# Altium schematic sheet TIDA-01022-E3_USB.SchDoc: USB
size 431 x 279 mm; Date: Not shown in title block; ApprovedBy: Not shown in title block; CheckedBy: Not shown in title block; Author: Not shown in title block; CompanyName: Not shown in title block; DrawnBy: Avinash N; Engineer: Not shown in title block; Organization: Not shown in title block; Address1: Not shown in title block; Address2: Not shown in title block; Address3: Not shown in title block; Address4: Not shown in title block; DocumentNumber: 1; Revision: Use project parameter SCH_Rev; SheetNumber: 16; SheetTotal: 26; PageSetup: Record=PageOptions¦CenterHorizontal=True¦CenterVertical=True¦PrintScale=1.00¦XCorrection=1.00¦YCorrection=1.00¦PrintKind=0¦BorderSize=5000000¦LeftOffset=0¦BottomOffset=0¦Orientation=2¦PaperLength=1000¦PaperWidth=1000¦Scale=100¦PaperSource=15¦PrintQuality=600¦MediaType=1¦DitherType=10¦PaperKind=Letter¦PrintScaleMode=1
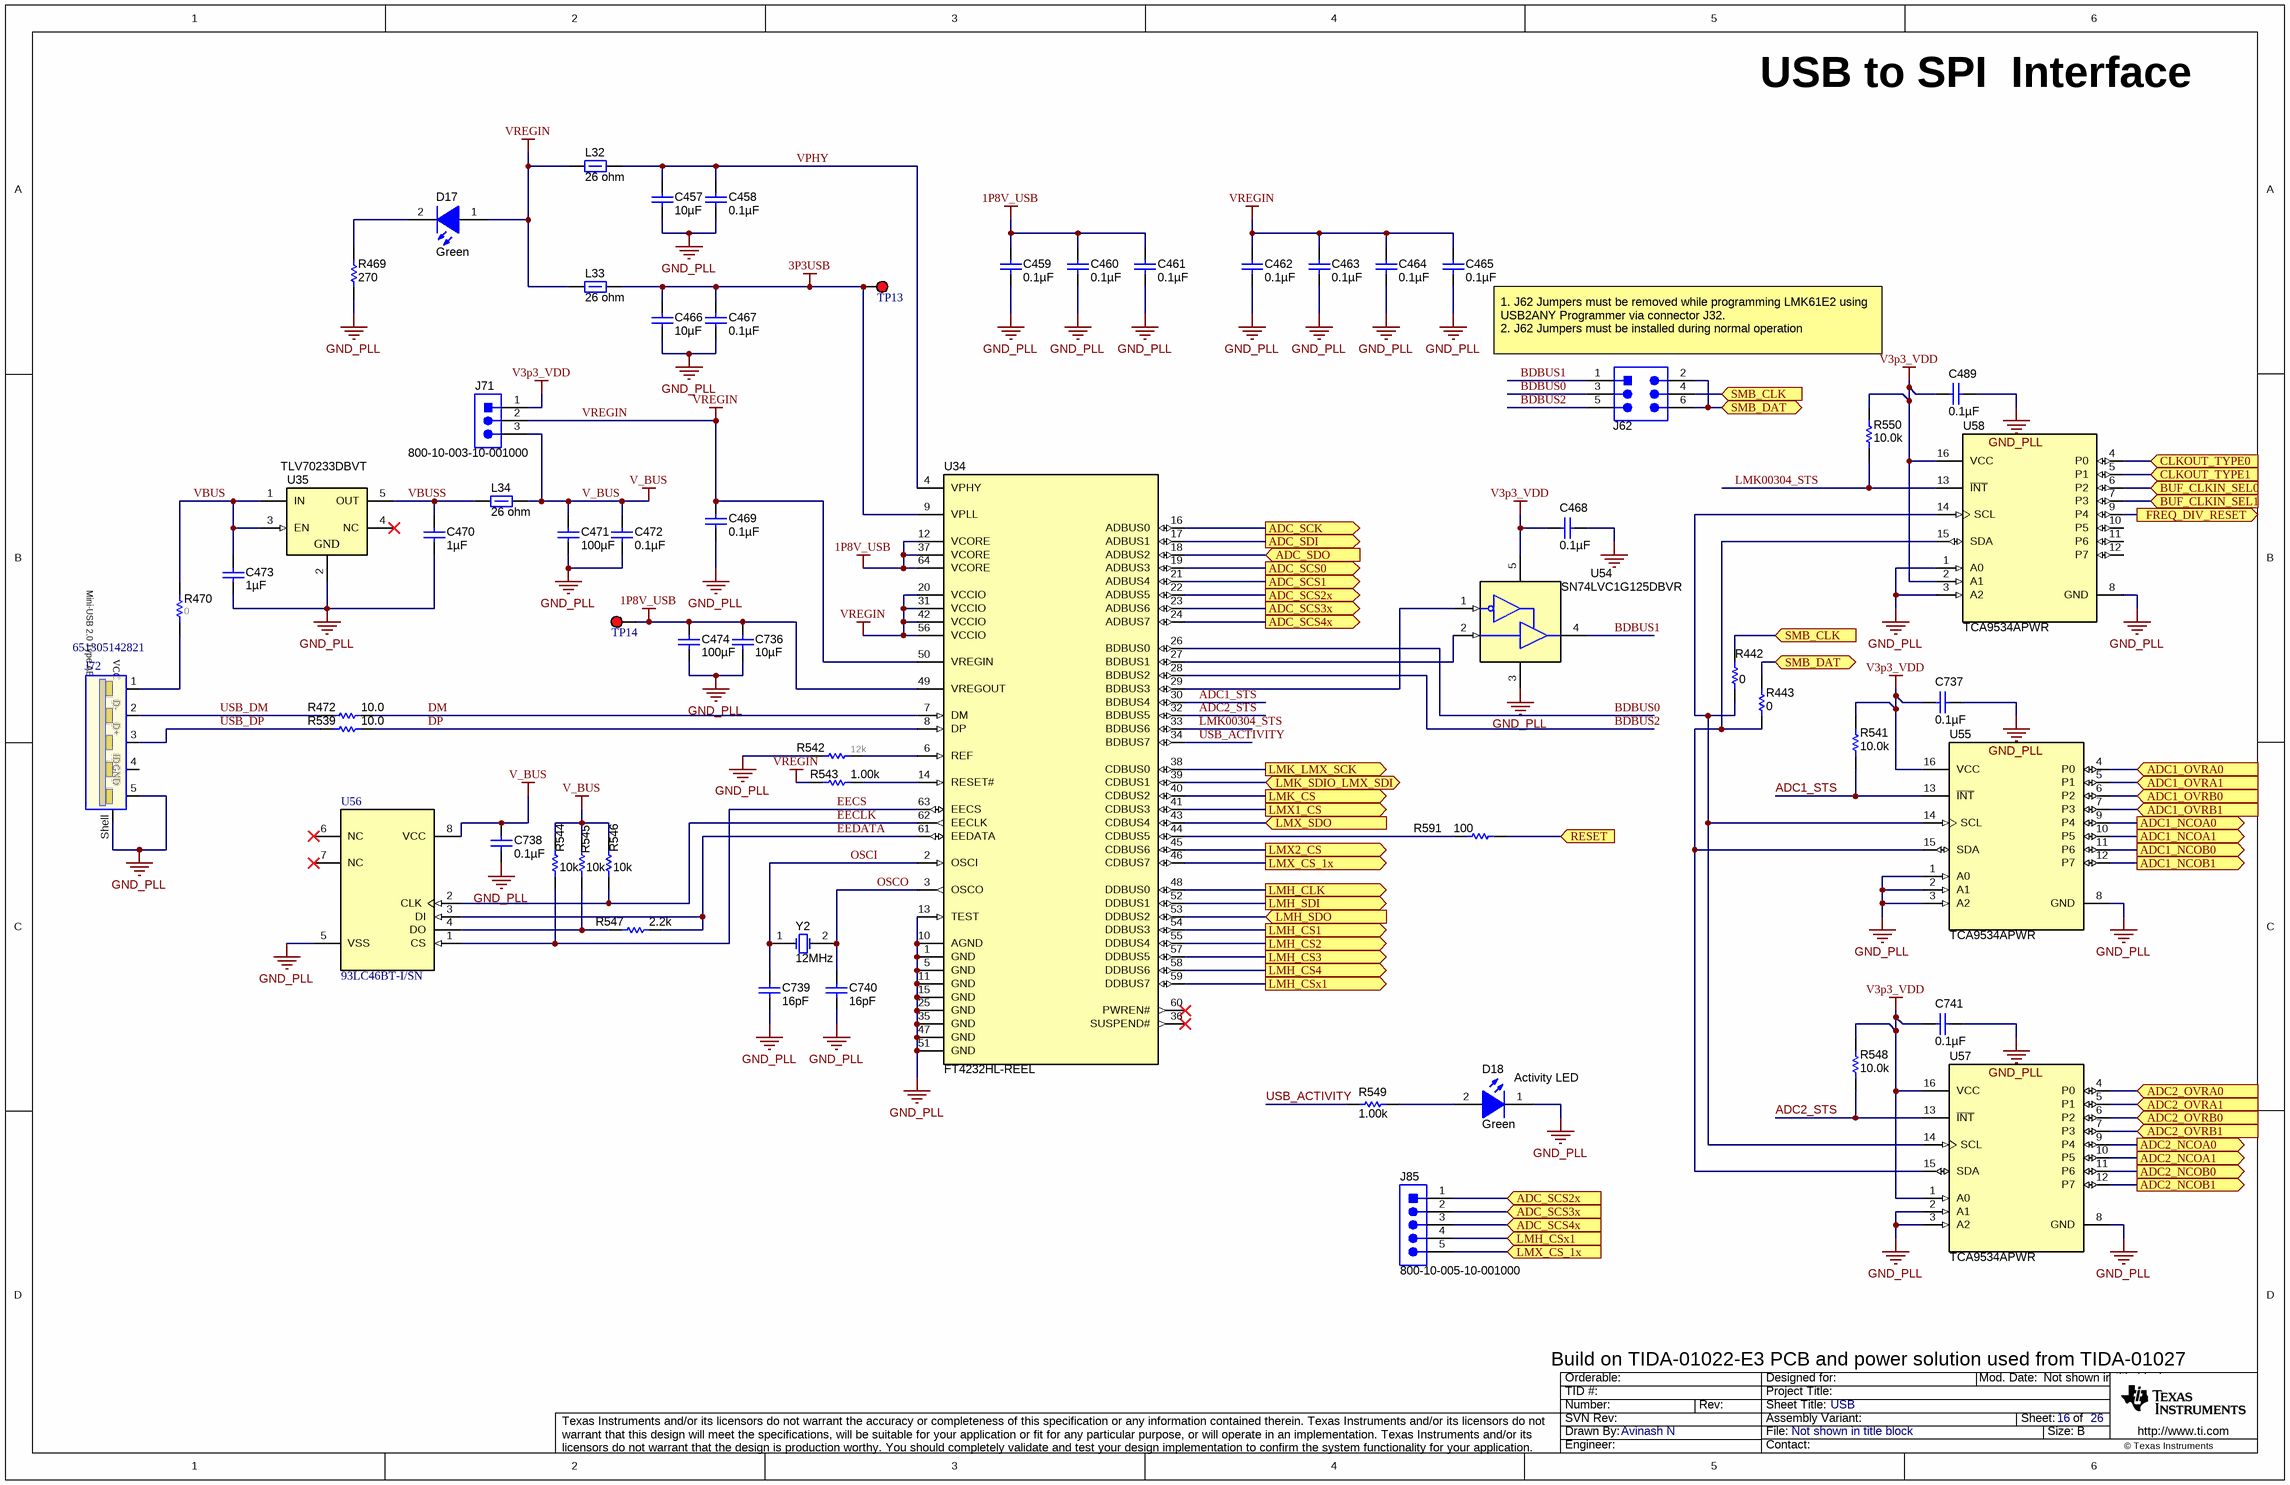
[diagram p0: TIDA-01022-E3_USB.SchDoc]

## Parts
C457  ValueDisplayed: 10µF  [0603]  (hidden comment: GRM188R61A106ME69D)
C458  ValueDisplayed: 0.1µF  [0603]  (hidden comment: C0603C104J3RACTU)
C459  ValueDisplayed: 0.1µF  [0603]  (hidden comment: C0603C104J3RACTU)
C460  ValueDisplayed: 0.1µF  [0603]  (hidden comment: C0603C104J3RACTU)
C461  ValueDisplayed: 0.1µF  [0603]  (hidden comment: C0603C104J3RACTU)
C462  ValueDisplayed: 0.1µF  [0603]  (hidden comment: C0603C104J3RACTU)
C463  ValueDisplayed: 0.1µF  [0603]  (hidden comment: C0603C104J3RACTU)
C464  ValueDisplayed: 0.1µF  [0603]  (hidden comment: C0603C104J3RACTU)
C465  ValueDisplayed: 0.1µF  [0603]  (hidden comment: C0603C104J3RACTU)
C466  ValueDisplayed: 10µF  [0603]  (hidden comment: GRM188R61A106ME69D)
C467  ValueDisplayed: 0.1µF  [0603]  (hidden comment: C0603C104J3RACTU)
C468  ValueDisplayed: 0.1µF  [0603]  (hidden comment: C0603C104J3RACTU)
C469  ValueDisplayed: 0.1µF  [0603]  (hidden comment: C0603C104J3RACTU)
C470  ValueDisplayed: 1µF  [0603]  (hidden comment: C1608X7R1C105K080AC)
C471  ValueDisplayed: 100µF  [1210_270]  (hidden comment: GRM32ER61A107ME20L)
C472  ValueDisplayed: 0.1µF  [0603]  (hidden comment: C0603C104J3RACTU)
C473  ValueDisplayed: 1µF  [0603]  (hidden comment: C1608X7R1C105K080AC)
C474  ValueDisplayed: 100µF  [1210_270]  (hidden comment: GRM32ER61A107ME20L)
C489  ValueDisplayed: 0.1µF  [0603]  (hidden comment: C0603C104J3RACTU)
C736  ValueDisplayed: 10µF  [0603]  (hidden comment: GRM188R61A106ME69D)
C737  ValueDisplayed: 0.1µF  [0603]  (hidden comment: C0603C104J3RACTU)
C738  ValueDisplayed: 0.1µF  [0603]  (hidden comment: C0603C104J3RACTU)
C739  ValueDisplayed: 16pF  [0603]  (hidden comment: GRM1885C2A160JA01D)
C740  ValueDisplayed: 16pF  [0603]  (hidden comment: GRM1885C2A160JA01D)
C741  ValueDisplayed: 0.1µF  [0603]  (hidden comment: C0603C104J3RACTU)
D17  value Green  [LTST-C191_Green]  (hidden comment: LTST-C191TGKT)
D18  value Green  [WL-SMCW_Green_0805]  (hidden comment: 150080GS75000)
J62  802-10-006-10-001000  [Mill-Max_802-10-006-10-001000]  (value not drawn)
J71  800-10-003-10-001000  [Mill-Max_800-10-003-10-001000]
J72  651305142821  [651305142821]
J85  800-10-005-10-001000  [Mill-Max_800-10-005-10-001000]
L32  ValueDisplayed: 26 ohm  [0603]  (hidden comment: BLM18SG260TN1D)
L33  ValueDisplayed: 26 ohm  [0603]  (hidden comment: BLM18SG260TN1D)
L34  ValueDisplayed: 26 ohm  [0603]  (hidden comment: BLM18SG260TN1D)
R442  ValueDisplayed: 0  [0603]  (hidden comment: CRCW06030000Z0EA)
R443  ValueDisplayed: 0  [0603]  (hidden comment: CRCW06030000Z0EA)
R469  ValueDisplayed: 270  [0603]  (hidden comment: CRCW0603270RJNEA)
R470  value 0  [0603]  (hidden comment: CRCW06030000Z0EA)
R472  ValueDisplayed: 10.0  [0603]  (hidden comment: CRCW060310R0FKEAHP)
R539  ValueDisplayed: 10.0  [0603]  (hidden comment: CRCW060310R0FKEAHP)
R541  ValueDisplayed: 10.0k  [1206]  (hidden comment: RC1206FR-0710KL)
R542  value 12k  [0603]  (hidden comment: CRCW060312K0JNEA)
R543  ValueDisplayed: 1.00k  [0603]  (hidden comment: CRCW06031K00FKEA)
R544  ValueDisplayed: 10k  [0603]  (hidden comment: CRCW060310K0JNEA)
R545  ValueDisplayed: 10k  [0603]  (hidden comment: CRCW060310K0JNEA)
R546  ValueDisplayed: 10k  [0603]  (hidden comment: CRCW060310K0JNEA)
R547  ValueDisplayed: 2.2k  [0603]  (hidden comment: CRCW06032K20JNEA)
R548  ValueDisplayed: 10.0k  [1206]  (hidden comment: RC1206FR-0710KL)
R549  ValueDisplayed: 1.00k  [0603]  (hidden comment: CRCW06031K00FKEA)
R550  ValueDisplayed: 10.0k  [1206]  (hidden comment: RC1206FR-0710KL)
R591  ValueDisplayed: 100  [0603]  (hidden comment: RC0603FR-07100RL)
TP13  5000  [Keystone5000]  (value not drawn)
TP14  5000  [Keystone5000]  (value not drawn)
U34  FT4232HL-REEL  [LQFP64_N]
U35  TLV70233DBVT  [DBV0005A_N]
U54  SN74LVC1G125DBVR  [DBV0005A_N]
U55  TCA9534APWR  [PW0016A_N]
U56  93LC46BT-I/SN  [SOIC-8]
U57  TCA9534APWR  [PW0016A_N]
U58  TCA9534APWR  [PW0016A_N]
Y2  Frequency: 12MHz  [XTAL_ABM3]  (hidden comment: ABM3-12.000MHZ-D2Y-T)

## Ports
ADC1_NCOA0 (out), ADC1_NCOA1 (out), ADC1_NCOB0 (out), ADC1_NCOB1 (out), ADC1_OVRA0 (in), ADC1_OVRA1 (in), ADC1_OVRB0 (in), ADC1_OVRB1 (in), ADC2_NCOA0 (out), ADC2_NCOA1 (out), ADC2_NCOB0 (out), ADC2_NCOB1 (out), ADC2_OVRA0 (in), ADC2_OVRA1 (in), ADC2_OVRB0 (in), ADC2_OVRB1 (in), ADC_SCK (out), ADC_SCS0 (out), ADC_SCS1 (out), ADC_SCS2x (in), ADC_SCS2x (out), ADC_SCS3x (in), ADC_SCS3x (out), ADC_SCS4x (in), ADC_SCS4x (out), ADC_SDI (out), ADC_SDO (in), BUF_CLKIN_SEL0 (in), BUF_CLKIN_SEL1 (in), CLKOUT_TYPE0 (in), CLKOUT_TYPE1 (in), FREQ_DIV_RESET (out), LMH_CLK (out), LMH_CS1 (out), LMH_CS2 (out), LMH_CS3 (out), LMH_CS4 (out), LMH_CSx1 (in), LMH_CSx1 (out), LMH_SDI (out), LMH_SDO (in), LMK_CS (out), LMK_LMX_SCK (out), LMK_SDIO_LMX_SDI (bidir), LMX1_CS (out), LMX2_CS (out), LMX_CS_1x (in), LMX_CS_1x (out), LMX_SDO (in), RESET (in), SMB_CLK (in), SMB_DAT (bidir)

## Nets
1P8V_USB: C459.2 C460.2 C461.2 C474.1 C736.1 TP14.1 U34.12(VCORE) U34.37(VCORE) U34.49(VREGOUT) U34.64(VCORE)
3P3USB: C466.1 C467.2 L33.2 TP13.1 U34.9(VPLL)
GND_PLL: C457.2 C458.1 C459.1 C460.1 C461.1 C462.1 C463.1 C464.1 C465.1 C466.2 C467.1 C468.1 C469.1 C470.2 C471.2 C472.1 C473.2 C474.2 C489.1 C736.2 C737.1 C738.1 C739.2 C740.2 C741.1 D18.1(K) J72.5(GND) J72.Shell R469.1 R542.2 U34.1(GND) U34.5(GND) U34.10(AGND) U34.11(GND) U34.13(TEST) U34.15(GND) U34.25(GND) U34.35(GND) U34.47(GND) U34.51(GND) U35.2(GND) U54.3(GND) U55.1(A0) U55.2(A1) U55.3(A2) U55.8(GND) U56.5(VSS) U57.2(A1) U57.3(A2) U57.8(GND) U58.1(A0) U58.3(A2) U58.8(GND)
V3p3_VDD: C468.2 C489.2 C737.2 C741.2 J71.1 R541.2 R548.2 R550.2 U54.5(VCC) U55.16(VCC) U57.1(A0) U57.16(VCC) U58.2(A1) U58.16(VCC)
V_BUS: C471.1 C472.2 C738.2 J71.3 L34.2 R544.2 R545.2 R546.2 U56.8(VCC)
VREGIN: C462.2 C463.2 C464.2 C465.2 C469.2 D17.1(A) J71.2 L32.1 L33.1 R543.1 U34.20(VCCIO) U34.31(VCCIO) U34.42(VCCIO) U34.50(VREGIN) U34.56(VCCIO)
ADC1_NCOA0: U55.9(P4) ; port ADC1_NCOA0
ADC1_NCOA1: U55.10(P5) ; port ADC1_NCOA1
ADC1_NCOB0: U55.11(P6) ; port ADC1_NCOB0
ADC1_NCOB1: U55.12(P7) ; port ADC1_NCOB1
ADC1_OVRA0: U55.4(P0) ; port ADC1_OVRA0
ADC1_OVRA1: U55.5(P1) ; port ADC1_OVRA1
ADC1_OVRB0: U55.6(P2) ; port ADC1_OVRB0
ADC1_OVRB1: U55.7(P3) ; port ADC1_OVRB1
ADC1_STS: R541.1 U34.30(BDBUS4) U55.13(~{INT})
ADC2_NCOA0: U57.9(P4) ; port ADC2_NCOA0
ADC2_NCOA1: U57.10(P5) ; port ADC2_NCOA1
ADC2_NCOB0: U57.11(P6) ; port ADC2_NCOB0
ADC2_NCOB1: U57.12(P7) ; port ADC2_NCOB1
ADC2_OVRA0: U57.4(P0) ; port ADC2_OVRA0
ADC2_OVRA1: U57.5(P1) ; port ADC2_OVRA1
ADC2_OVRB0: U57.6(P2) ; port ADC2_OVRB0
ADC2_OVRB1: U57.7(P3) ; port ADC2_OVRB1
ADC2_STS: R548.1 U34.32(BDBUS5) U57.13(~{INT})
ADC_SCK: U34.16(ADBUS0) ; port ADC_SCK
ADC_SCS0: U34.19(ADBUS3) ; port ADC_SCS0
ADC_SCS1: U34.21(ADBUS4) ; port ADC_SCS1
ADC_SCS2x: J85.1 U34.22(ADBUS5) ; port ADC_SCS2x
ADC_SCS3x: J85.2 U34.23(ADBUS6) ; port ADC_SCS3x
ADC_SCS4x: J85.3 U34.24(ADBUS7) ; port ADC_SCS4x
ADC_SDI: U34.17(ADBUS1) ; port ADC_SDI
ADC_SDO: U34.18(ADBUS2) ; port ADC_SDO
BDBUS0: J62.3 U34.26(BDBUS0)
BDBUS1: J62.1 U54.4(Y)
BDBUS2: J62.5 U34.28(BDBUS2)
BUF_CLKIN_SEL0: U58.6(P2) ; port BUF_CLKIN_SEL0
BUF_CLKIN_SEL1: U58.7(P3) ; port BUF_CLKIN_SEL1
CLKOUT_TYPE0: U58.4(P0) ; port CLKOUT_TYPE0
CLKOUT_TYPE1: U58.5(P1) ; port CLKOUT_TYPE1
DM: R472.2 U34.7(DM)
DP: R539.2 U34.8(DP)
EECLK: R546.1 U34.62(EECLK) U56.2(CLK)
EECS: R544.1 U34.63(EECS) U56.1(CS)
EEDATA: R547.2 U34.61(EEDATA) U56.3(DI)
FREQ_DIV_RESET: U58.9(P4) ; port FREQ_DIV_RESET
LMH_CLK: U34.48(DDBUS0) ; port LMH_CLK
LMH_CS1: U34.54(DDBUS3) ; port LMH_CS1
LMH_CS2: U34.55(DDBUS4) ; port LMH_CS2
LMH_CS3: U34.57(DDBUS5) ; port LMH_CS3
LMH_CS4: U34.58(DDBUS6) ; port LMH_CS4
LMH_CSx1: J85.4 U34.59(DDBUS7) ; port LMH_CSx1
LMH_SDI: U34.52(DDBUS1) ; port LMH_SDI
LMH_SDO: U34.53(DDBUS2) ; port LMH_SDO
LMK00304_STS: R550.1 U34.33(BDBUS6) U58.13(~{INT})
LMK_CS: U34.40(CDBUS2) ; port LMK_CS
LMK_LMX_SCK: U34.38(CDBUS0) ; port LMK_LMX_SCK
LMK_SDIO_LMX_SDI: U34.39(CDBUS1) ; port LMK_SDIO_LMX_SDI
LMX1_CS: U34.41(CDBUS3) ; port LMX1_CS
LMX2_CS: U34.45(CDBUS6) ; port LMX2_CS
LMX_CS_1x: J85.5 U34.46(CDBUS7) ; port LMX_CS_1x
LMX_SDO: U34.43(CDBUS4) ; port LMX_SDO
OSCI: C739.1 U34.2(OSCI) Y2.1(OSC1)
OSCO: C740.1 U34.3(OSCO) Y2.2(OSC2)
RESET: R591.2 ; port RESET
SMB_CLK: J62.4 R442.2 ; port SMB_CLK
SMB_DAT: J62.2 J62.6 R443.2 ; port SMB_DAT
USB_ACTIVITY: R549.1 U34.34(BDBUS7)
USB_DM: J72.2(D-) R472.1
USB_DP: J72.3(D+) R539.1
VBUS: C473.1 R470.2 U35.1(IN) U35.3(EN)
VBUSS: C470.1 L34.1 U35.5(OUT)
VPHY: C457.1 C458.2 L32.2 U34.4(VPHY)
NetD17_2: D17.2(K) R469.2
NetD18_2: D18.2(A) R549.2
NetJ72_1: J72.1(VCC) R470.1
NetR442_1: R442.1 U55.14(SCL) U57.14(SCL) U58.14(SCL)
NetR443_1: R443.1 U55.15(SDA) U57.15(SDA) U58.15(SDA)
NetR542_1: R542.1 U34.6(REF)
NetR543_2: R543.2 U34.14(RESET#)
NetR545_1: R545.1 R547.1 U56.4(DO)
NetR591_1: R591.1 U34.44(CDBUS5)
NetU34_27: U34.27(BDBUS1) U54.2(A)
NetU34_29: U34.29(BDBUS3) U54.1(~{OE})

Not connected (* = marked no-connect by the designer): J72 4(ID); U34 36(SUSPEND#)* 60(PWREN#)*; U35 4(NC)*; U56 6(NC)* 7(NC)*; U58 10(P5) 11(P6) 12(P7)

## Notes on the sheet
- USB to SPI  Interface
- 1. J62 Jumpers must be removed while programming LMK61E2 using      USB2ANY Programmer via connector J32.
  2. J62 Jumpers must be installed during normal operation
- (near D18) Activity LED
- Build on TIDA-01022-E3 PCB and power solution used from TIDA-01027

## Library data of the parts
C457 C466 C736 = GRM188R61A106ME69D: CAP, CERM, 10 µF, 10 V, +/- 20%, X5R, 0603; Manufacturer: MuRata; Polarized: N; CompType: Capacitor; Value: 10uF; U/M: EA; Cap_F: 0.00001; Tolerance_%: 20; Value1: Unknown; VDC_V: 10; Value2: 10V; TaMin_C: -55; TaMax_C: 85; SizeArea_mm2: 1.28; SizeAreaWB_mm2: 4.68; SizeX_mm: 1.6; SizeY_mm: 0.8; SizeZ_mm: 1; AEC Category: Q200
C458-C465 C467-C469 C472 C489 C737 C738 C741 = C0603C104J3RACTU: CAP, CERM, 0.1uF, 25V, +/-5%, X7R, 0603; Manufacturer: Kemet; Polarized: N; TaMax_C: 125; TaMin_C: -55; Tolerance_%: 5; VDC_V: 25; Cap_F: 0.0000001; CompType: Capacitor; Value1: Unknown; U/M: EA
C470 C473 = C1608X7R1C105K080AC: CAP, CERM, 1 µF, 16 V, +/- 10%, X7R, 0603; Manufacturer: TDK; Polarized: N; CompType: Capacitor; Value: 1uF; U/M: EA; Cap_F: 0.000001; Tolerance_%: 10; ESR_ohm: 0.0057; Value1: 0.0057 ohm; VDC_V: 16; Value2: 16V; TaMin_C: -55; TaMax_C: 125; SizeArea_mm2: 1.28; SizeAreaWB_mm2: 4.68; SizeX_mm: 1.6; SizeY_mm: 0.8; SizeZ_mm: 1; AEC Category: Q200
C471 C474 = GRM32ER61A107ME20L: CAP, CERM, 100 µF, 10 V, +/- 20%, X5R, 1210; Manufacturer: MuRata; Polarized: N; CompType: Capacitor; Value: 100uF; U/M: EA; Cap_F: 0.0001; Tolerance_%: 20; Value1: Unknown; VDC_V: 10; Value2: 10V; TaMin_C: -55; TaMax_C: 85; Cap_Case: 1210; SizeArea_mm2: 8; SizeAreaWB_mm2: 14.7; SizeX_mm: 3.2; SizeY_mm: 2.5; SizeZ_mm: 2.7; AEC Category: Q200
C739 C740 = GRM1885C2A160JA01D: CAP, CERM, 16 pF, 100 V, +/- 5%, C0G/NP0, 0603; Manufacturer: MuRata; Polarized: N; CompType: Capacitor; Value: 16pF; U/M: EA; Cap_F: 0.000000000016; Tolerance_%: 5; Value1: Unknown; VDC_V: 100; Value2: 100V; TaMin_C: -55; TaMax_C: 125; SizeArea_mm2: 1.28; SizeAreaWB_mm2: 4.68; SizeX_mm: 1.6; SizeY_mm: 0.8; SizeZ_mm: 1; AEC Category: Q200
D17 = LTST-C191TGKT: LED, Green, SMD; Manufacturer: Lite-On; Type: InGaN; Vf_V: 3.2; Value2: 3.2V; Io_A: 0.02; Value1: W; U/M: EA
D18 = 150080GS75000: LED, Green, SMD; Manufacturer: Wurth Elektronik; Type: InGaN; Vf_V: 3.2; Value2: 3.2V; Io_A: 0.02; Vr_V: 5; Ir_A: 1e-005; Tjmax_C: 85; Power_TotalModule: 0.105; Value1: 0.105W; Angle: 140; U/M: EA
J62 = 802-10-006-10-001000: Header, 2.54 mm, 3x2, Gold, TH; Manufacturer: Mill-Max; SymbolCreator: a0412235; Pitch_mm: 2.54; Gender: Male; Shrouded: N; Row_Count: 2
J71 = 800-10-003-10-001000: Header, 100mil, 3x1, TH; Manufacturer: Mill-Max; SymbolCreator: a0799628
J72 = 651305142821: WR-COM Mini USB 2.0 Type AB SMT Horizontal 5 Contacts
J85 = 800-10-005-10-001000: Header, 100mil, 5x1, TH; Manufacturer: Mill-Max; SymbolCreator: a0412235
L32-L34 = BLM18SG260TN1D: Ferrite Bead, 26 ohm @ 100 MHz, 6 A, 0603; Manufacturer: MuRata; Value: 26 ohm; Imax_A: 6; DCR_ohm: 0.007; Value1: 0.007 ohm; Value2: 6A; SizeAreaWB_mm2: 4.68; SizeArea_mm2: 1.28; SizeX_mm: 1.6; SizeY_mm: 0.8; SizeZ_mm: 1; ZTyp@100MHz_Ohm: 26
R442 R443 = CRCW06030000Z0EA: RES, 0, 5%, 0.1 W, 0603; Manufacturer: Vishay-Dale; CompType: Resistor; Value: 0; Value_Code: 0000; Tolerance_%: 5; Power_W: 0.1; Value2: 0.1W; VDC_V: 75; TempCo: 200 ppm/C; SizeArea_mm2: 1.28; SizeX_mm: 1.6; SizeY_mm: 0.8; SizeZ_mm: 1; EIA_Code: E24; U/M: EA; AEC Category: Q200
R469 = CRCW0603270RJNEA: RES, 270, 5%, 0.1 W, 0603; Manufacturer: Vishay-Dale; CompType: Resistor; Value: 270; Value_Code: 270R; Tolerance_%: 5; Power_W: 0.1; Value2: 0.1W; VDC_V: 75; TempCo: 200 ppm/C; SizeArea_mm2: 1.28; SizeX_mm: 1.6; SizeY_mm: 0.8; SizeZ_mm: 1; EIA_Code: E24; U/M: EA; AEC Category: Q200
R470 = CRCW06030000Z0EA: RES, 0 ohm, 5%, 0.1W, 0603; Manufacturer: Vishay-Dale; CompType: Resistor; Tolerance_%: 5; VDC_V: 75; Power_W: 0.1; U/M: EA; Value_Code: 0000; EIA_Code: E24
R472 R539 = CRCW060310R0FKEAHP: RES, 10.0, 1%, 0.25 W, 0603; Manufacturer: Vishay-Dale; CompType: Resistor; Value: 10.0; Res_ohm: 10; Value_Code: 10R0; Tolerance_%: 1; Power_W: 0.25; Value2: 0.25W; VDC_V: 75; TempCo: 100 ppm/C; SizeArea_mm2: 1.28; SizeX_mm: 1.6; SizeY_mm: 0.8; EIA_Code: E96; U/M: EA; AEC Category: Q200
R541 R548 R550 = RC1206FR-0710KL: RES, 10.0 k, 1%, 0.25 W, 1206; Manufacturer: Yageo America; CompType: Resistor; Value: 10.0k; Res_ohm: 10000; Value_Code: 10k0; Tolerance_%: 1; Power_W: 0.25; Value2: 0.25W; VDC_V: 200; TempCo: 100 ppm/C; SizeArea_mm2: 5.12; SizeX_mm: 3.2; SizeY_mm: 1.6; SizeZ_mm: 1.35; EIA_Code: E96; U/M: EA; AEC Category: Q200
R542 = CRCW060312K0JNEA: RES, 12k ohm, 5%, 0.1W, 0603; Manufacturer: Vishay-Dale; CompType: Resistor; Tolerance_%: 5; VDC_V: 75; Power_W: 0.1; Res_ohm: 12000; U/M: EA; Value_Code: 12k0; EIA_Code: E24
R543 R549 = CRCW06031K00FKEA: RES, 1.00 k, 1%, 0.1 W, 0603; Manufacturer: Vishay-Dale; CompType: Resistor; Value: 1.00k; Res_ohm: 1000; Value_Code: 1k00; Tolerance_%: 1; Power_W: 0.1; Value2: 0.1W; VDC_V: 75; TempCo: 100 ppm/C; SizeArea_mm2: 1.28; SizeX_mm: 1.6; SizeY_mm: 0.8; EIA_Code: E96; U/M: EA; AEC Category: Q200
R544-R546 = CRCW060310K0JNEA: RES, 10 k, 5%, 0.1 W, 0603; Manufacturer: Vishay-Dale; CompType: Resistor; Value: 10k; Res_ohm: 10000; Value_Code: 10k0; Tolerance_%: 5; Power_W: 0.1; Value2: 0.1W; VDC_V: 75; TempCo: 200 ppm/C; SizeArea_mm2: 1.28; SizeX_mm: 1.6; SizeY_mm: 0.8; SizeZ_mm: 1; EIA_Code: E24; U/M: EA; AEC Category: Q200
R547 = CRCW06032K20JNEA: RES, 2.2 k, 5%, 0.1 W, 0603; Manufacturer: Vishay-Dale; CompType: Resistor; Value: 2.2k; Res_ohm: 2200; Value_Code: 2k20; Tolerance_%: 5; Power_W: 0.1; Value2: 0.1W; VDC_V: 75; TempCo: 200 ppm/C; SizeArea_mm2: 1.28; SizeX_mm: 1.6; SizeY_mm: 0.8; SizeZ_mm: 1; EIA_Code: E24; U/M: EA; AEC Category: Q200
R591 = RC0603FR-07100RL: RES, 100, 1%, 0.1 W, 0603; Manufacturer: Yageo America; CompType: Resistor; Value: 100; Value_Code: 100R; Tolerance_%: 1; Power_W: 0.1; Value2: 0.1W; VDC_V: 150; TempCo: 200 ppm/C; SizeArea_mm2: 1.28; SizeX_mm: 1.6; SizeY_mm: 0.8; EIA_Code: E96; U/M: EA; AEC Category: Q200
TP13 TP14 = 5000: Test Point, Miniature, Red, TH; Manufacturer: Keystone; CompType: Test Point Loop; ContactFinish: Silver
U34 = FT4232HL: Quad High Speed USB to Multipurpose UART/MPSSE IC; Manufacturer: FTDI; SymbolCreator: a0411947
U35 = TLV70233DBVT: Single Output LDO, 300 mA, Fixed 3.3 V Output, 2 to 5.5 V Input, with Low IQ, 5-pin SOT-23 (DBV), -40 to 125 degC, Green (RoHS & no Sb/Br); Manufacturer: Texas Instruments; Alternate PartNumber: Equivalent; Accuracy(%): 2; Fixed Output Options(V): 3.3; Iout(Max)(A): 0.3; Iq(Typ)(mA): 0.03; SubFamily: Single Channel LDO; Vdo(Typ)(mV): 220; Vin(Max)(V): 5.5
U54 = SN74LVC1G125DBVR: Single Bus Buffer Gate With 3-State Outputs, DBV0005A (SOT-5); Alternate PartNumber: SN74LVC1G125DBVT; Manufacturer: Texas Instruments; SymbolCreator: Altium; SizeArea_mm2: 8.12; SizeAreaWB_mm2: 14.82; SizeX_mm: 2.8; SizeY_mm: 2.9; SizeZ_mm: 1.45; CompType: IC; U/M: EA
U55 U57 U58 = TCA9534APWR: Remote 8-Bit I2C and Low-Power I/O Expander With Interrupt Output and Configuration Registers, PW0016A (TSSOP-16); Manufacturer: Texas Instruments; SymbolCreator: Altium; SizeArea_mm2: 32; SizeAreaWB_mm2: 58.8; SizeX_mm: 6.4; SizeY_mm: 5; SizeZ_mm: 1.2; CompType: IC; U/M: EA
U56 = 93LC46BT-I/SN: 1K Microwire Compatible Serial EEPROM; Manufacturer: Microchip; SymbolCreator: Altium; SizeAreaWB_mm2: 55.131; SizeArea_mm2: 29.351; SizeX_mm: 5.99; SizeY_mm: 4.9; SizeZ_mm: 1.75
Y2 = ABM3-12.000MHZ-D2Y-T: Crystal, 12 MHz, 18 pF, SMD; Manufacturer: Abracon Corporation; SymbolCreator: a0412235; U/M: EA; TaMin_C: -40; TaMax_C: 85; Frequency Stability: ±30ppm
